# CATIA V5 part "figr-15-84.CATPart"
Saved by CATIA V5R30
Part number: Part1
Bounding box of the stored display mesh (mm): x 0 to 27, y -46 to 46, z -30 to 30
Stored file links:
  D:\PROJECTS\CATIA V56R 2020\Resources\Parts File\c15_catia_v5_6r2020_prt\figr-15-84.CATPart
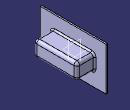
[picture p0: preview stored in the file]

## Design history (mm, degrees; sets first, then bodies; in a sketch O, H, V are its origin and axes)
SheetMetalParameters1: Thickness 2, BendRadius 4, KFactor 0.400515 {= log(min(100,max(20*SheetMetalParameters1.BendRadius,SheetMetalParameters1.Thickness)/SheetMetalParameters1.Thickness))/log(100)/2}, ReliefRadialLength 1, ReliefAxialLength 2, MinimumBendRadius 0
Body1 (main body)
  Sketch1 on yz-plane, origin (0, 0, 0), H (0, 1, 0), V (0, 0, 1)
    line L1 (46, 30) -> (46, -30)
    line L2 (46, -30) -> (-46, -30)
    line L3 (-46, -30) -> (-46, 30)
    line L4 (-46, 30) -> (46, 30)
    vertical: L1 V, L3 V
    horizontal: L2 H, L4 H
    equidistance: L1 L3 O, L2 L4 O
  Wall1: Thickness 2, Profile Sketch1, OffsetValue 0
  Sketch2 on face of Wall1, origin (2, 0, 0), H (0, 1, 0), V (0, 0, 1)
    line L1 (28, 9) -> (28, -9)
    line L2 (28, -9) -> (-28, -9)
    line L3 (-28, -9) -> (-28, 9)
    line L4 (-28, 9) -> (28, 9)
    vertical: L1 V, L3 V
    horizontal: L2 H, L4 H
    equidistance: L1 L3 O, L2 L4 O
  d_Stamp1: NewRoot_AttribNormalisation "No Standard", Stamp_FilletRadius 2, Stamp_IntersectFilletRadius 2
